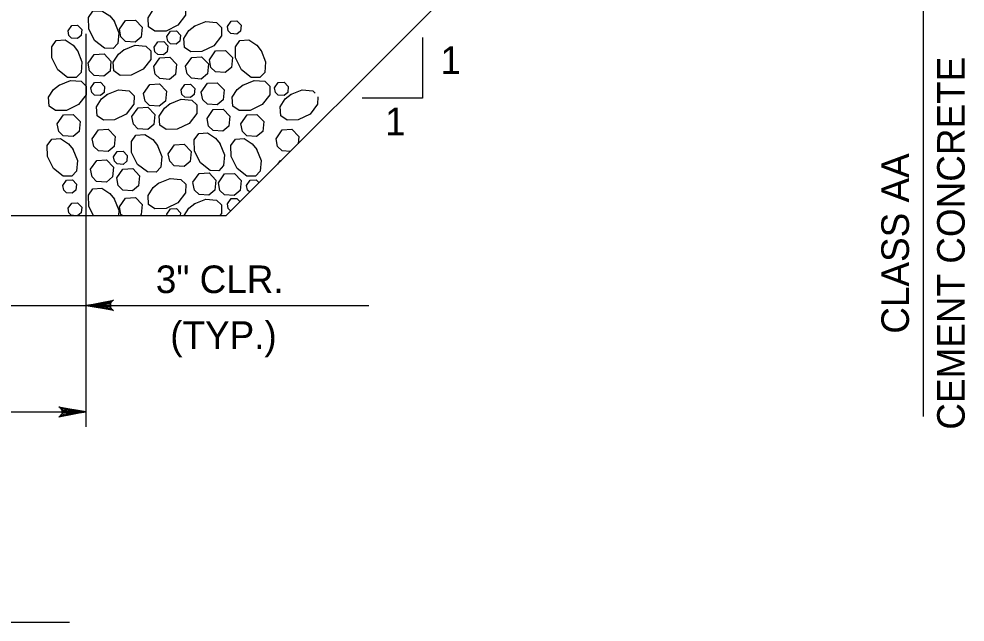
# Model space of a CAD drawing. Extents: x 638079 to 640019, y 297691 to 298879.
# Drawn here: x 639410.8 to 639513.8, y 298663.4 to 298729 of the extents above; entities that cross this region are included whole.
import ezdxf

# ---------------------------------------------------------------- set-up
doc = ezdxf.new("R2010")
doc.units = 0
doc.layers.add('1', color=7, linetype='Continuous')

msp = doc.modelspace()

# ---------------------------------------------------------------- linework, layer by layer
at = {"layer": '1'}
for p, q in [((639433.38, 298707.6), (639484.18, 298758.39)), ((639509.26, 298685.76), (639509.26, 298737.64)), ((639418.14, 298684.62), (639418.14, 298727.36)), ((639454.74, 298726.97), (639454.74, 298720.39)), ((639454.74, 298720.39), (639448.15, 298720.39)), ((639250.5, 298707.6), (639433.38, 298707.6)), ((639402.82, 298697.84), (639448.88, 298697.84)), ((639224.58, 298686.26), (639418.14, 298686.26)), ((639272.75, 298663.4), (639416.31, 298663.4))]:
    msp.add_line(p, q, dxfattribs=at)
for points in [[(639426, 298730.45), (639427.26, 298730.95), (639428.42, 298730.85), (639428.96, 298730.33), (639428.95, 298729.39), (639428.11, 298728.33), (639426.83, 298727.68), (639425.61, 298727.66), (639424.93, 298728.15), (639424.86, 298729.11), (639425.42, 298729.98), (639426.05, 298730.48)], [(639421.18, 298728.75), (639421.68, 298727.49), (639421.58, 298726.34), (639421.05, 298725.79), (639420.12, 298725.81), (639419.05, 298726.64), (639418.41, 298727.93), (639418.39, 298729.14), (639418.87, 298729.83), (639419.84, 298729.89), (639420.7, 298729.34), (639421.21, 298728.7)], [(639421.75, 298727.87), (639422.42, 298728.82), (639423.49, 298728.88), (639424.24, 298728.11), (639424.13, 298727.03), (639423.47, 298726.48), (639422.41, 298726.55), (639421.91, 298727.04), (639421.75, 298727.87)], [(639429.9, 298728.21), (639431.16, 298728.7), (639432.32, 298728.6), (639432.87, 298728.08), (639432.85, 298727.14), (639432.02, 298726.08), (639430.73, 298725.44), (639429.51, 298725.41), (639428.83, 298725.9), (639428.77, 298726.87), (639429.32, 298727.73), (639429.95, 298728.24)], [(639433.5, 298728.19), (639433.9, 298728.76), (639434.54, 298728.8), (639434.99, 298728.33), (639434.93, 298727.68), (639434.53, 298727.35), (639433.89, 298727.4), (639433.59, 298727.69), (639433.5, 298728.19)], [(639416.16, 298727.71), (639416.56, 298728.29), (639417.2, 298728.32), (639417.65, 298727.86), (639417.59, 298727.21), (639417.19, 298726.88), (639416.55, 298726.92), (639416.25, 298727.21), (639416.16, 298727.71)], [(639426.91, 298727.08), (639427.31, 298727.66), (639427.95, 298727.69), (639428.4, 298727.23), (639428.34, 298726.58), (639427.94, 298726.25), (639427.3, 298726.29), (639427, 298726.58), (639426.91, 298727.08)], [(639417.17, 298725.58), (639417.67, 298724.32), (639417.57, 298723.17), (639417.05, 298722.62), (639416.11, 298722.64), (639415.05, 298723.47), (639414.4, 298724.76), (639414.38, 298725.97), (639414.87, 298726.65), (639415.83, 298726.72), (639416.7, 298726.16), (639417.2, 298725.53)], [(639425.52, 298725.92), (639425.92, 298726.49), (639426.57, 298726.53), (639427.02, 298726.06), (639426.95, 298725.41), (639426.55, 298725.08), (639425.92, 298725.13), (639425.62, 298725.42), (639425.52, 298725.92)], [(639437.16, 298725.58), (639437.66, 298724.32), (639437.56, 298723.17), (639437.04, 298722.62), (639436.1, 298722.64), (639435.03, 298723.47), (639434.39, 298724.76), (639434.37, 298725.97), (639434.85, 298726.65), (639435.82, 298726.72), (639436.69, 298726.16), (639437.19, 298725.53)], [(639422.22, 298725.64), (639423.48, 298726.14), (639424.63, 298726.04), (639425.18, 298725.52), (639425.16, 298724.58), (639424.33, 298723.52), (639423.04, 298722.87), (639421.83, 298722.85), (639421.14, 298723.34), (639421.08, 298724.3), (639421.63, 298725.17), (639422.27, 298725.68)], [(639431.55, 298724.56), (639432.22, 298725.51), (639433.3, 298725.57), (639434.04, 298724.8), (639433.94, 298723.72), (639433.27, 298723.16), (639432.21, 298723.24), (639431.71, 298723.72), (639431.55, 298724.56)], [(639418.34, 298724.17), (639419.01, 298725.13), (639420.09, 298725.19), (639420.83, 298724.41), (639420.73, 298723.33), (639420.06, 298722.78), (639419, 298722.85), (639418.5, 298723.34), (639418.34, 298724.17)], [(639425.48, 298723.81), (639426.15, 298724.77), (639427.22, 298724.83), (639427.97, 298724.06), (639427.86, 298722.97), (639427.2, 298722.42), (639426.14, 298722.5), (639425.64, 298722.98), (639425.48, 298723.81)], [(639428.94, 298723.85), (639429.62, 298724.81), (639430.69, 298724.87), (639431.44, 298724.1), (639431.33, 298723.01), (639430.66, 298722.46), (639429.6, 298722.54), (639429.11, 298723.02), (639428.94, 298723.85)], [(639415.18, 298721.81), (639416.44, 298722.31), (639417.59, 298722.21), (639418.14, 298721.69), (639418.12, 298720.75), (639417.29, 298719.68), (639416, 298719.04), (639414.79, 298719.02), (639414.1, 298719.5), (639414.04, 298720.47), (639414.59, 298721.33), (639415.23, 298721.84)], [(639418.65, 298721.51), (639419.05, 298722.09), (639419.7, 298722.12), (639420.14, 298721.66), (639420.08, 298721.01), (639419.68, 298720.68), (639419.04, 298720.72), (639418.75, 298721.01), (639418.65, 298721.51)], [(639424.37, 298720.9), (639425.05, 298721.86), (639426.12, 298721.92), (639426.86, 298721.14), (639426.76, 298720.06), (639426.09, 298719.51), (639425.03, 298719.58), (639424.54, 298720.07), (639424.37, 298720.9)], [(639428.45, 298721.29), (639428.86, 298721.87), (639429.5, 298721.9), (639429.95, 298721.44), (639429.88, 298720.79), (639429.48, 298720.46), (639428.85, 298720.5), (639428.55, 298720.79), (639428.45, 298721.29)], [(639430.66, 298721.04), (639431.33, 298722), (639432.4, 298722.06), (639433.15, 298721.29), (639433.04, 298720.2), (639432.38, 298719.65), (639431.32, 298719.73), (639430.82, 298720.21), (639430.66, 298721.04)], [(639435.17, 298721.81), (639436.42, 298722.31), (639437.58, 298722.21), (639438.13, 298721.69), (639438.11, 298720.75), (639437.28, 298719.68), (639435.99, 298719.04), (639434.78, 298719.02), (639434.09, 298719.5), (639434.03, 298720.47), (639434.58, 298721.33), (639435.22, 298721.84)], [(639438.64, 298721.51), (639439.04, 298722.09), (639439.68, 298722.12), (639440.13, 298721.66), (639440.07, 298721.01), (639439.67, 298720.68), (639439.03, 298720.72), (639438.73, 298721.01), (639438.64, 298721.51)], [(639420.39, 298720.78), (639421.65, 298721.27), (639422.8, 298721.18), (639423.35, 298720.65), (639423.33, 298719.72), (639422.5, 298718.65), (639421.21, 298718.01), (639420, 298717.99), (639419.32, 298718.47), (639419.25, 298719.44), (639419.81, 298720.3), (639420.44, 298720.81)], [(639443.34, 298720.52), (639443.32, 298719.72), (639442.49, 298718.65), (639441.2, 298718.01), (639439.99, 298717.99), (639439.3, 298718.47), (639439.24, 298719.44), (639439.79, 298720.3), (639440.43, 298720.81)], [(639440.38, 298720.78), (639441.64, 298721.27), (639442.79, 298721.18), (639443.05, 298720.93)], [(639423.11, 298718.37), (639423.78, 298719.33), (639424.85, 298719.39), (639425.6, 298718.61), (639425.49, 298717.53), (639424.83, 298716.98), (639423.77, 298717.05), (639423.27, 298717.54), (639423.11, 298718.37)], [(639427.22, 298719.76), (639428.48, 298720.26), (639429.64, 298720.16), (639430.18, 298719.64), (639430.17, 298718.7), (639429.33, 298717.63), (639428.05, 298716.99), (639426.83, 298716.97), (639426.15, 298717.45), (639426.08, 298718.42), (639426.64, 298719.29), (639427.27, 298719.79)], [(639414.97, 298717.6), (639415.65, 298718.55), (639416.72, 298718.61), (639417.47, 298717.84), (639417.36, 298716.76), (639416.7, 298716.2), (639415.64, 298716.28), (639415.14, 298716.76), (639414.98, 298717.6)], [(639431.29, 298718.18), (639431.96, 298719.14), (639433.03, 298719.2), (639433.78, 298718.43), (639433.67, 298717.34), (639433.01, 298716.79), (639431.95, 298716.87), (639431.45, 298717.35), (639431.29, 298718.18)], [(639434.96, 298717.6), (639435.64, 298718.55), (639436.71, 298718.61), (639437.45, 298717.84), (639437.35, 298716.76), (639436.68, 298716.2), (639435.62, 298716.28), (639435.13, 298716.76), (639434.96, 298717.6)], [(639418.8, 298715.97), (639419.47, 298716.93), (639420.54, 298716.99), (639421.29, 298716.21), (639421.18, 298715.13), (639420.52, 298714.58), (639419.46, 298714.65), (639418.96, 298715.14), (639418.8, 298715.97)], [(639425.85, 298715.29), (639426.35, 298714.04), (639426.25, 298712.88), (639425.73, 298712.33), (639424.79, 298712.35), (639423.73, 298713.18), (639423.08, 298714.47), (639423.06, 298715.68), (639423.55, 298716.37), (639424.52, 298716.43), (639425.38, 298715.88), (639425.89, 298715.24)], [(639432.69, 298715.46), (639433.19, 298714.2), (639433.09, 298713.04), (639432.56, 298712.49), (639431.63, 298712.51), (639430.56, 298713.35), (639429.92, 298714.63), (639429.9, 298715.85), (639430.38, 298716.53), (639431.35, 298716.6), (639432.21, 298716.04), (639432.72, 298715.41)], [(639438.79, 298715.97), (639439.46, 298716.93), (639440.53, 298716.99), (639441.28, 298716.21), (639441.2, 298715.41)], [(639416.68, 298714.85), (639417.18, 298713.59), (639417.08, 298712.43), (639416.56, 298711.88), (639415.62, 298711.9), (639414.56, 298712.74), (639413.91, 298714.02), (639413.89, 298715.24), (639414.38, 298715.92), (639415.34, 298715.99), (639416.21, 298715.43), (639416.72, 298714.8)], [(639427.06, 298714.34), (639427.73, 298715.3), (639428.81, 298715.36), (639429.55, 298714.59), (639429.45, 298713.5), (639428.78, 298712.95), (639427.72, 298713.03), (639427.22, 298713.51), (639427.06, 298714.34)], [(639436.67, 298714.85), (639437.17, 298713.59), (639437.07, 298712.43), (639436.55, 298711.88), (639435.61, 298711.9), (639434.55, 298712.74), (639433.9, 298714.02), (639433.88, 298715.24), (639434.37, 298715.92), (639435.33, 298715.99), (639436.2, 298715.43), (639436.7, 298714.8)], [(639440.37, 298714.59), (639439.45, 298714.65), (639438.95, 298715.14), (639438.79, 298715.97)], [(639421.11, 298714.01), (639421.51, 298714.58), (639422.15, 298714.62), (639422.6, 298714.16), (639422.54, 298713.51), (639422.14, 298713.17), (639421.5, 298713.22), (639421.2, 298713.51), (639421.11, 298714.01)], [(639418.61, 298712.65), (639419.28, 298713.6), (639420.35, 298713.67), (639421.1, 298712.89), (639420.99, 298711.81), (639420.33, 298711.26), (639419.27, 298711.33), (639418.77, 298711.82), (639418.61, 298712.65)], [(639438.99, 298713.2), (639439.27, 298713.6), (639439.4, 298713.61)], [(639421.45, 298711.7), (639422.12, 298712.66), (639423.19, 298712.72), (639423.94, 298711.94), (639423.83, 298710.86), (639423.17, 298710.31), (639422.11, 298710.38), (639421.61, 298710.87), (639421.45, 298711.7)], [(639429.75, 298711.23), (639430.42, 298712.18), (639431.5, 298712.24), (639432.24, 298711.47), (639432.14, 298710.39), (639431.47, 298709.83), (639430.41, 298709.91), (639429.91, 298710.39), (639429.75, 298711.22)], [(639432.52, 298711.18), (639433.19, 298712.14), (639434.26, 298712.2), (639435.01, 298711.43), (639434.9, 298710.34), (639434.24, 298709.79), (639433.18, 298709.87), (639432.68, 298710.35), (639432.52, 298711.18)], [(639415.59, 298710.89), (639415.99, 298711.46), (639416.64, 298711.5), (639417.08, 298711.04), (639417.02, 298710.39), (639416.62, 298710.05), (639415.98, 298710.1), (639415.69, 298710.39), (639415.59, 298710.89)], [(639426, 298711.14), (639427.26, 298711.64), (639428.42, 298711.54), (639428.96, 298711.01), (639428.95, 298710.08), (639428.11, 298709.01), (639426.83, 298708.37), (639425.61, 298708.35), (639424.93, 298708.83), (639424.86, 298709.8), (639425.42, 298710.66), (639426.05, 298711.17)], [(639435.58, 298710.89), (639435.98, 298711.46), (639436.62, 298711.5), (639436.95, 298711.16)], [(639418.92, 298707.6), (639418.41, 298708.61), (639418.39, 298709.83), (639418.87, 298710.51), (639419.84, 298710.58), (639420.7, 298710.02), (639421.21, 298709.39)], [(639435.93, 298710.14), (639435.67, 298710.39), (639435.58, 298710.89)], [(639416.16, 298708.4), (639416.56, 298708.97), (639417.2, 298709.01), (639417.65, 298708.54), (639417.59, 298707.89), (639417.23, 298707.6)], [(639421.18, 298709.44), (639421.68, 298708.18), (639421.63, 298707.6)], [(639421.75, 298708.55), (639422.42, 298709.51), (639423.49, 298709.57), (639424.24, 298708.8), (639424.13, 298707.71), (639423.99, 298707.6)], [(639429.9, 298708.89), (639431.16, 298709.39), (639432.32, 298709.29), (639432.87, 298708.77), (639432.85, 298707.83), (639432.67, 298707.6)], [(639433.5, 298708.87), (639433.9, 298709.45), (639434.54, 298709.48), (639434.9, 298709.11)], [(639416.74, 298707.6), (639416.55, 298707.61), (639416.25, 298707.9), (639416.16, 298708.4)], [(639422.04, 298707.6), (639421.91, 298707.72), (639421.75, 298708.55)], [(639426.91, 298707.77), (639427.31, 298708.34), (639427.95, 298708.38), (639428.4, 298707.91), (639428.37, 298707.6)], [(639428.79, 298707.6), (639429.32, 298708.42), (639429.95, 298708.92)], [(639433.88, 298708.1), (639433.59, 298708.37), (639433.5, 298708.87)], [(639426.94, 298707.6), (639426.91, 298707.77)], [(639418.14, 298697.84), (639421.12, 298698.4), (639421.01, 298698.32), (639420.89, 298698.24), (639420.83, 298698.14), (639420.77, 298698.04), (639420.76, 298697.94), (639420.74, 298697.84), (639420.76, 298697.74), (639420.77, 298697.64), (639420.83, 298697.54), (639420.89, 298697.44), (639421.01, 298697.36), (639421.12, 298697.28), (639418.14, 298697.84), (639421.01, 298697.36), (639420.89, 298697.44), (639418.14, 298697.84), (639420.83, 298697.54), (639420.77, 298697.64), (639418.14, 298697.84), (639420.76, 298697.74), (639420.74, 298697.84), (639418.14, 298697.84), (639420.76, 298697.94), (639420.77, 298698.04), (639418.14, 298697.84), (639420.83, 298698.14), (639420.89, 298698.24), (639418.14, 298697.84), (639421.01, 298698.32)], [(639418.14, 298686.26), (639415.16, 298685.7), (639415.27, 298685.78), (639415.39, 298685.86), (639415.45, 298685.96), (639415.51, 298686.06), (639415.52, 298686.16), (639415.54, 298686.26), (639415.52, 298686.36), (639415.51, 298686.46), (639415.45, 298686.56), (639415.39, 298686.66), (639415.27, 298686.74), (639415.16, 298686.82), (639418.14, 298686.26), (639415.27, 298686.74), (639415.39, 298686.66), (639418.14, 298686.26), (639415.45, 298686.56), (639415.51, 298686.46), (639418.14, 298686.26), (639415.52, 298686.36), (639415.54, 298686.26), (639418.14, 298686.26), (639415.52, 298686.16), (639415.51, 298686.06), (639418.14, 298686.26), (639415.45, 298685.96), (639415.39, 298685.86), (639418.14, 298686.26), (639415.27, 298685.78)], [(639418.14, 298686.26), (639415.16, 298685.7), (639415.27, 298685.78), (639415.39, 298685.86), (639415.45, 298685.96), (639415.51, 298686.06), (639415.52, 298686.16), (639415.54, 298686.26), (639415.52, 298686.36), (639415.51, 298686.46), (639415.45, 298686.56), (639415.39, 298686.66), (639415.27, 298686.74), (639415.16, 298686.82), (639418.14, 298686.26), (639415.27, 298686.74), (639415.39, 298686.66), (639418.14, 298686.26), (639415.45, 298686.56), (639415.51, 298686.46), (639418.14, 298686.26), (639415.52, 298686.36), (639415.54, 298686.26), (639418.14, 298686.26), (639415.52, 298686.16), (639415.51, 298686.06), (639418.14, 298686.26), (639415.45, 298685.96), (639415.39, 298685.86), (639418.14, 298686.26), (639415.27, 298685.78)]]:
    msp.add_lwpolyline(points, dxfattribs=at)

# ---------------------------------------------------------------- texts
for s, p in [('1', (639456.68, 298723.01)), ('1', (639450.66, 298716.35)), ('3" CLR.', (639425.71, 298699.18)), ('(TYP.)', (639427.28, 298693.11))]:
    msp.add_text(s, height=3, dxfattribs=at).set_placement(p)
for s, p in [('CEMENT CONCRETE', (639513.74, 298684.32)), ('CLASS AA', (639507.67, 298694.76))]:
    msp.add_text(s, height=3, rotation=90, dxfattribs=at).set_placement(p)

doc.saveas('drawing.dxf')
